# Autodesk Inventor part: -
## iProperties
Shininess: 50.0
Length Units: 11272
Angle Units: 11279
Time Units: 11290
Mass Units: 11286
Length Display Precision: 3
Angle Display Precision: 2
Manager: Cory McConnell
Company: MechaniX Design Solutions
Part Number: -
Document SubType Name: Modeling
Designer: CM
Material: Cast Steel
Created: 2004-01
Manufacturer: Standard
Standards Organization: Custom
Description: 1/2 BEVEL WSHR
Density: 10.49
Volumn: 2.304646865681294
Area: 8.437628188859923
PropertySet Name: Model Information
Control State: 0
Master: False
Checked Out: False
PartAngTol0: 0.5 deg
PartAngTol1: 0.5 deg
PartAngTol2: 0.5 deg
PartAngTol3: 0.5 deg
PartAngTol4: 0.5 deg
PartLinTol1: 0.015 in
PartLinTol2: 0.01 in
PartLinTol3: 0.005 in
PartLinTol4: 0.001 in
Author: CM
Revision Number: 0
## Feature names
1. Extrusion3
2. Extrusion4
3. Fillet1
4. Hole1
